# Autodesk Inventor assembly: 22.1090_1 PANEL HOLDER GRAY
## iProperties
Created: 2007-05
Part Number: 22.1090_1 PANEL HOLDER GRAY
Document SubType Name: Assembly
Designer: Andy Moles
Author: Andy Moles
